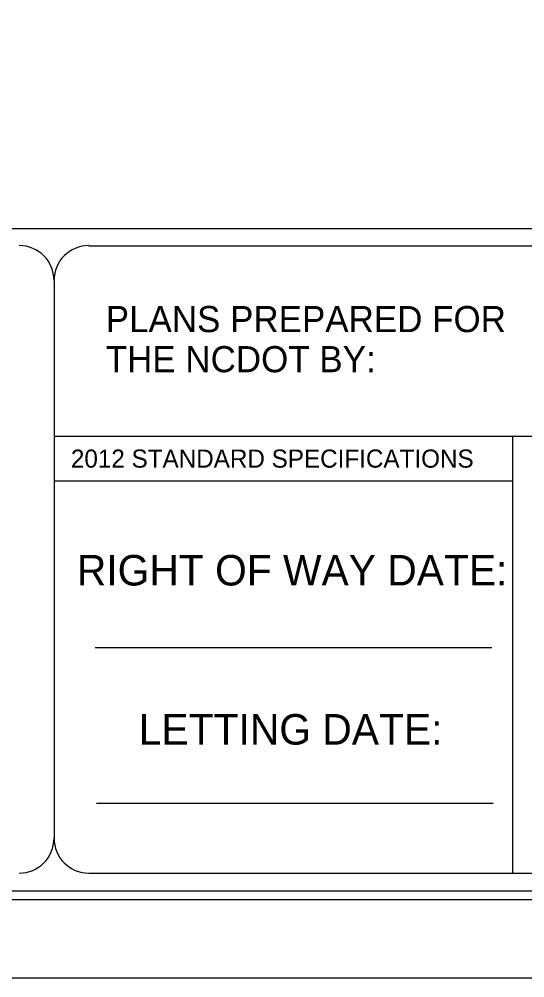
# Model space of a CAD drawing. Extents: x 2431000 to 2534000, y 645879 to 714000.
# Drawn here: x 2464804.7 to 2464949.7, y 678900 to 679175 of the extents above; entities that cross this region are included whole.
import ezdxf

# ---------------------------------------------------------------- set-up
doc = ezdxf.new("R2010")
doc.units = 0
for name, color, linetype in [('Prop Dimension', 7, 'Continuous'), ('Prop Dimension Text', 7, 'Continuous'), ('Prop Terminator CELL', 7, 'Continuous')]:
    doc.layers.add(name, color=color, linetype=linetype)

msp = doc.modelspace()

# ---------------------------------------------------------------- linework, layer by layer
at = {"layer": 'Prop Dimension'}
msp.add_lwpolyline([(2463853.2, 678900), (2465536.7, 678900), (2465536.7, 680000), (2463853.2, 680000)], close=True, dxfattribs=at)
at = {"layer": 'Prop Dimension Text'}
for p, q in [((2464084.7, 679115), (2465504.7, 679115)), ((2464824.7, 679110), (2465109.7, 679110)), ((2464814.7, 679100), (2464814.7, 678940)), ((2465119.7, 679055.24), (2464814.7, 679055.25)), ((2464946.25, 679055.25), (2464946.25, 678930)), ((2464946.25, 679042.49), (2464814.7, 679042.5)), ((2464908.35, 679042.5), (2464908.35, 679042.5)), ((2464940.25, 678994.65), (2464826.5, 678994.65)), ((2464883.35, 678994.64), (2464883.35, 678994.64)), ((2464940.65, 678950.05), (2464826.9, 678950.05))]:
    msp.add_line(p, q, dxfattribs=at)
for points in [[(2464824.7, 678930), (2465109.7, 678929.99)], [(2464029.7, 678924.99), (2465509.7, 678924.99)]]:
    msp.add_lwpolyline(points, dxfattribs=at)
for centre, start, end in [((2464804.7, 679100.04), 0, 90), ((2464824.7, 679100.04), 90, 180), ((2464804.7, 678940.04), 270, 0), ((2464824.7, 678940.04), 180, 270)]:
    msp.add_arc(centre, 10, start, end, dxfattribs=at)
at = {"layer": 'Prop Terminator CELL'}
msp.add_lwpolyline([(2463866.2, 678922.5), (2465532.2, 678922.5), (2465532.2, 679977.5), (2463866.2, 679977.5)], close=True, dxfattribs=at)

# ---------------------------------------------------------------- texts
at = {"layer": 'Prop Dimension Text'}
for s, height, p in [('PLANS PREPARED FOR ', 7.4994, (2464829.53, 679085.22)), ('THE NCDOT BY:', 7.4994, (2464829.53, 679073.72)), ('2012 STANDARD SPECIFICATIONS', 5.2, (2464819.54, 679046.35)), ('RIGHT OF WAY DATE: ', 8.7498, (2464821.25, 679012.55)), ('LETTING DATE:', 8.7498, (2464839.01, 678966.9))]:
    msp.add_text(s, height=height, dxfattribs=at).set_placement(p)

doc.saveas('drawing.dxf')
